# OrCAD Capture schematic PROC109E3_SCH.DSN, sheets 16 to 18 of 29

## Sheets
16 16. ETHERNET_MUX_SoC_ADC_IN: size C; title: ETHERNET DATA MUX & ADC INPUTS
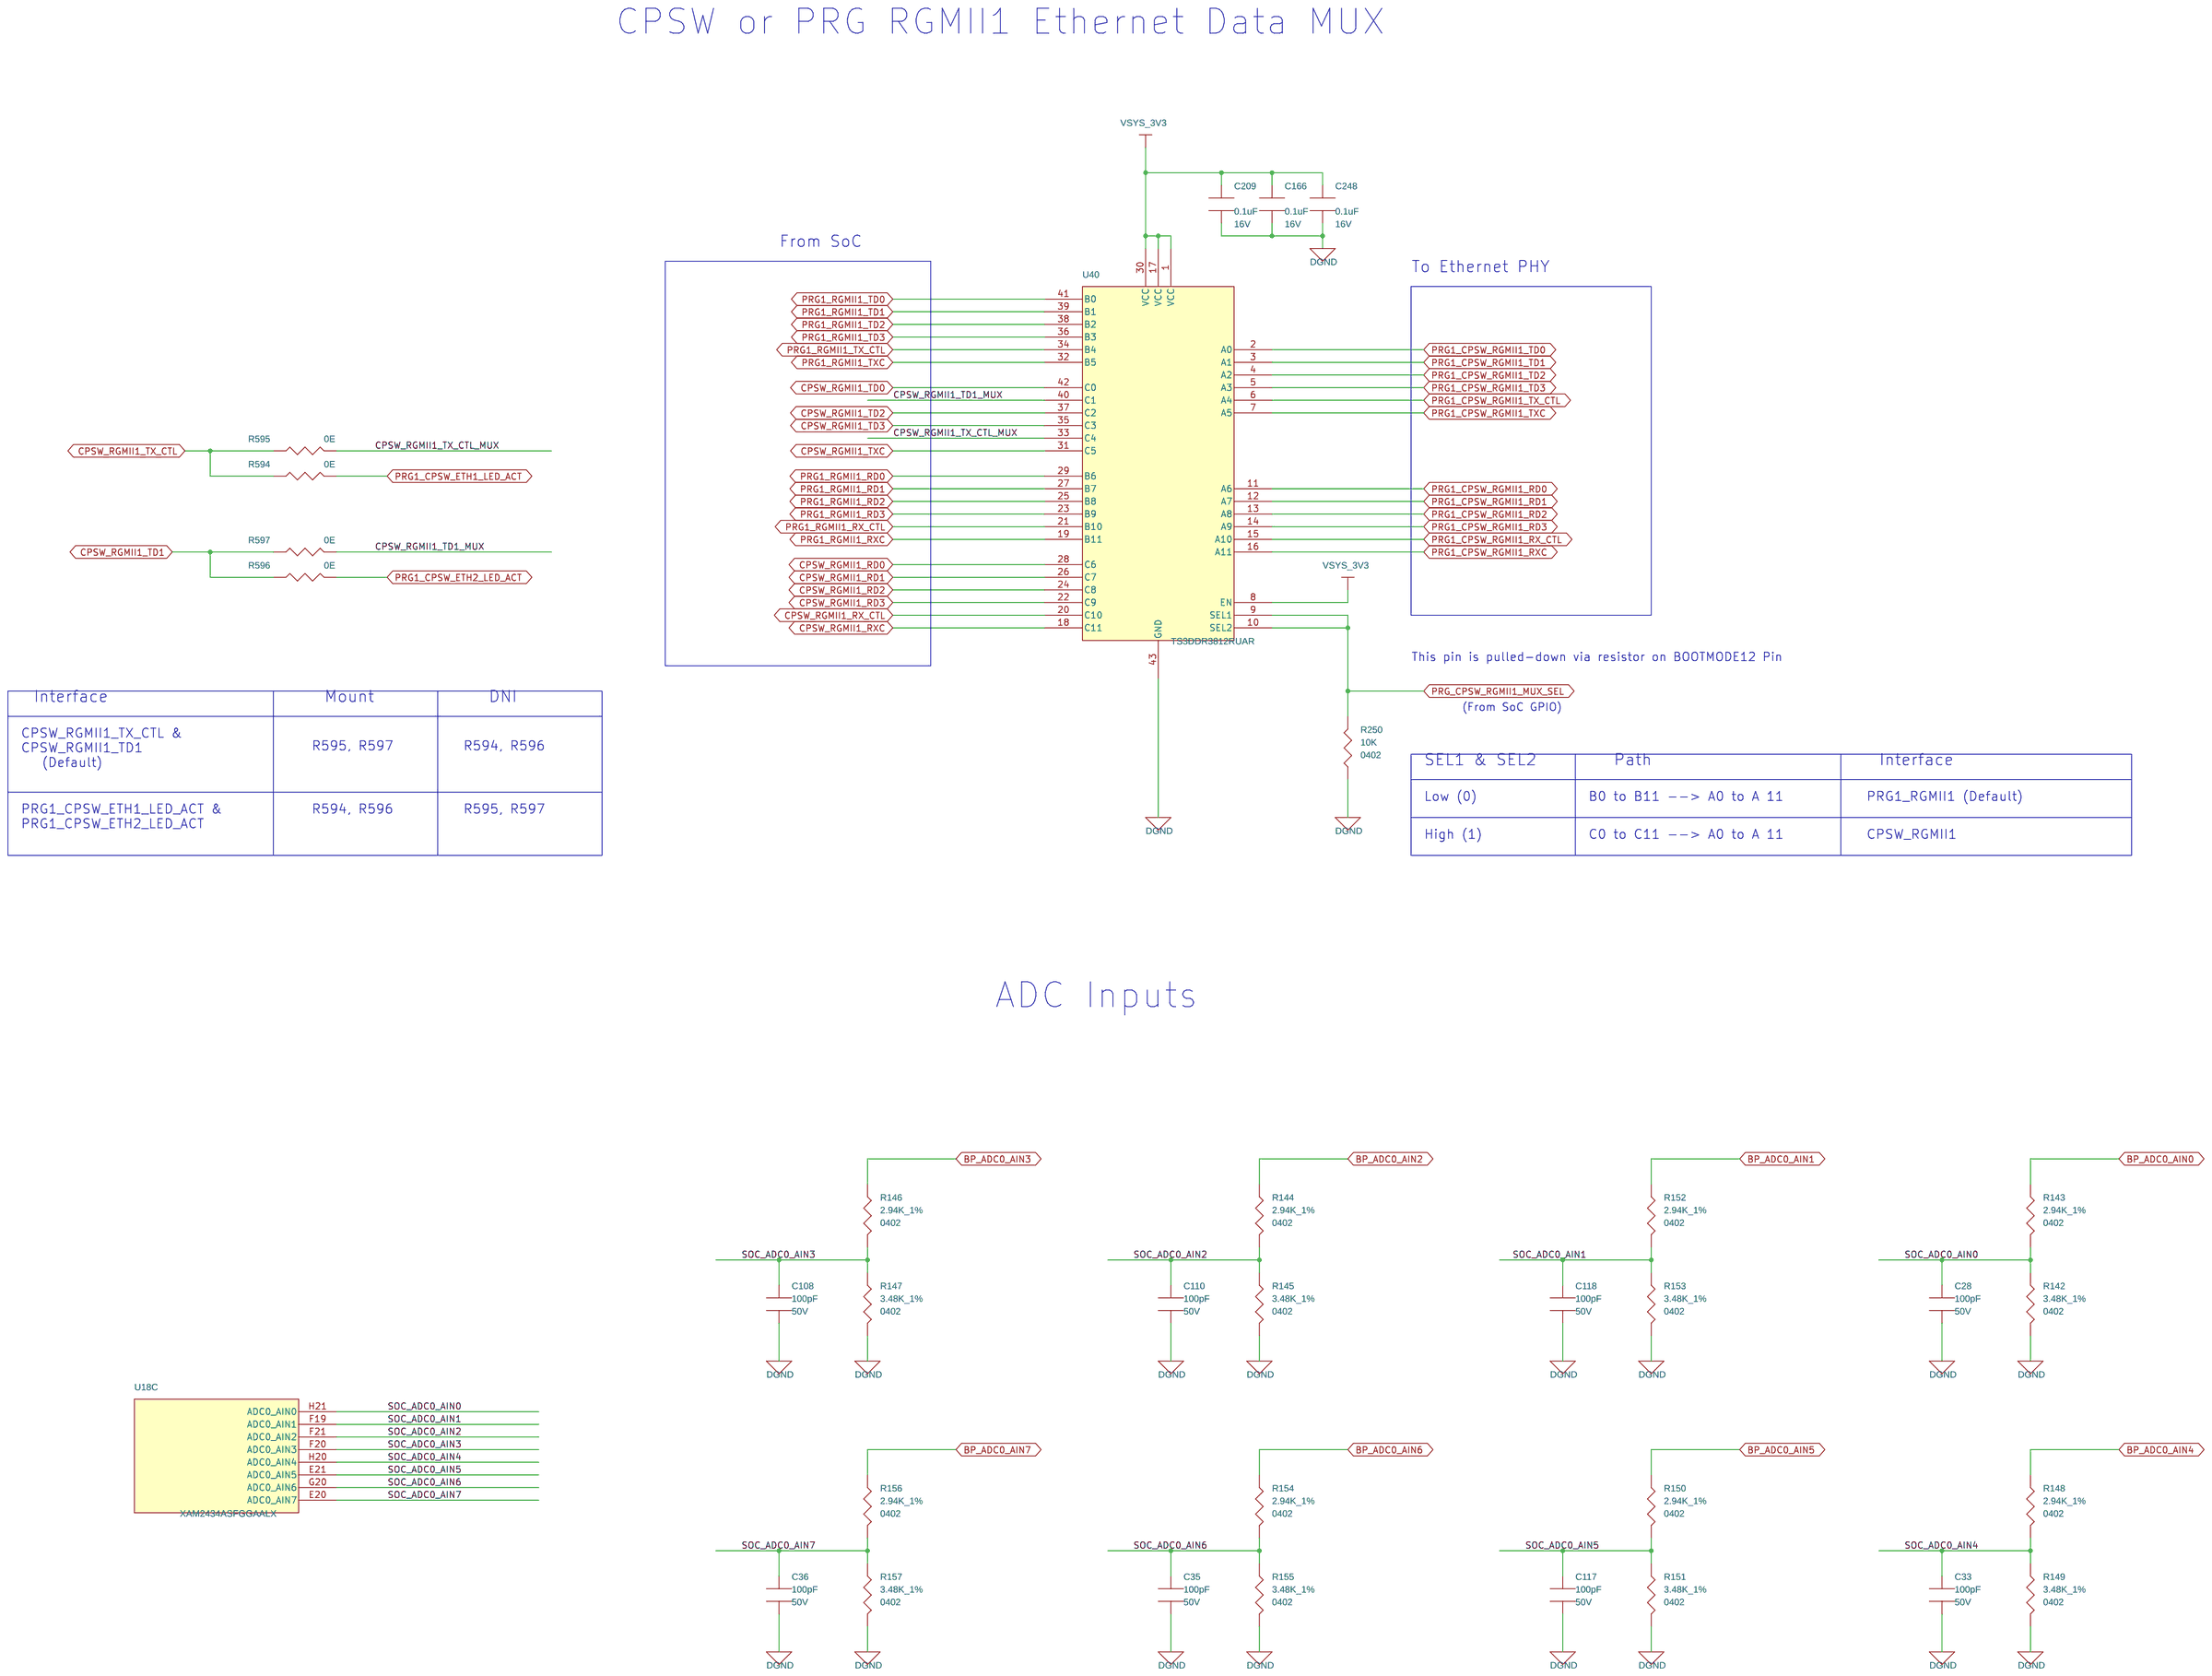
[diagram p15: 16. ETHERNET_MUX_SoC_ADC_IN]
17 17. CPSW_PRG_RGMII_1_EPHY: size C; title: PRG/CPSW RGMII1 ETHERNET PHY
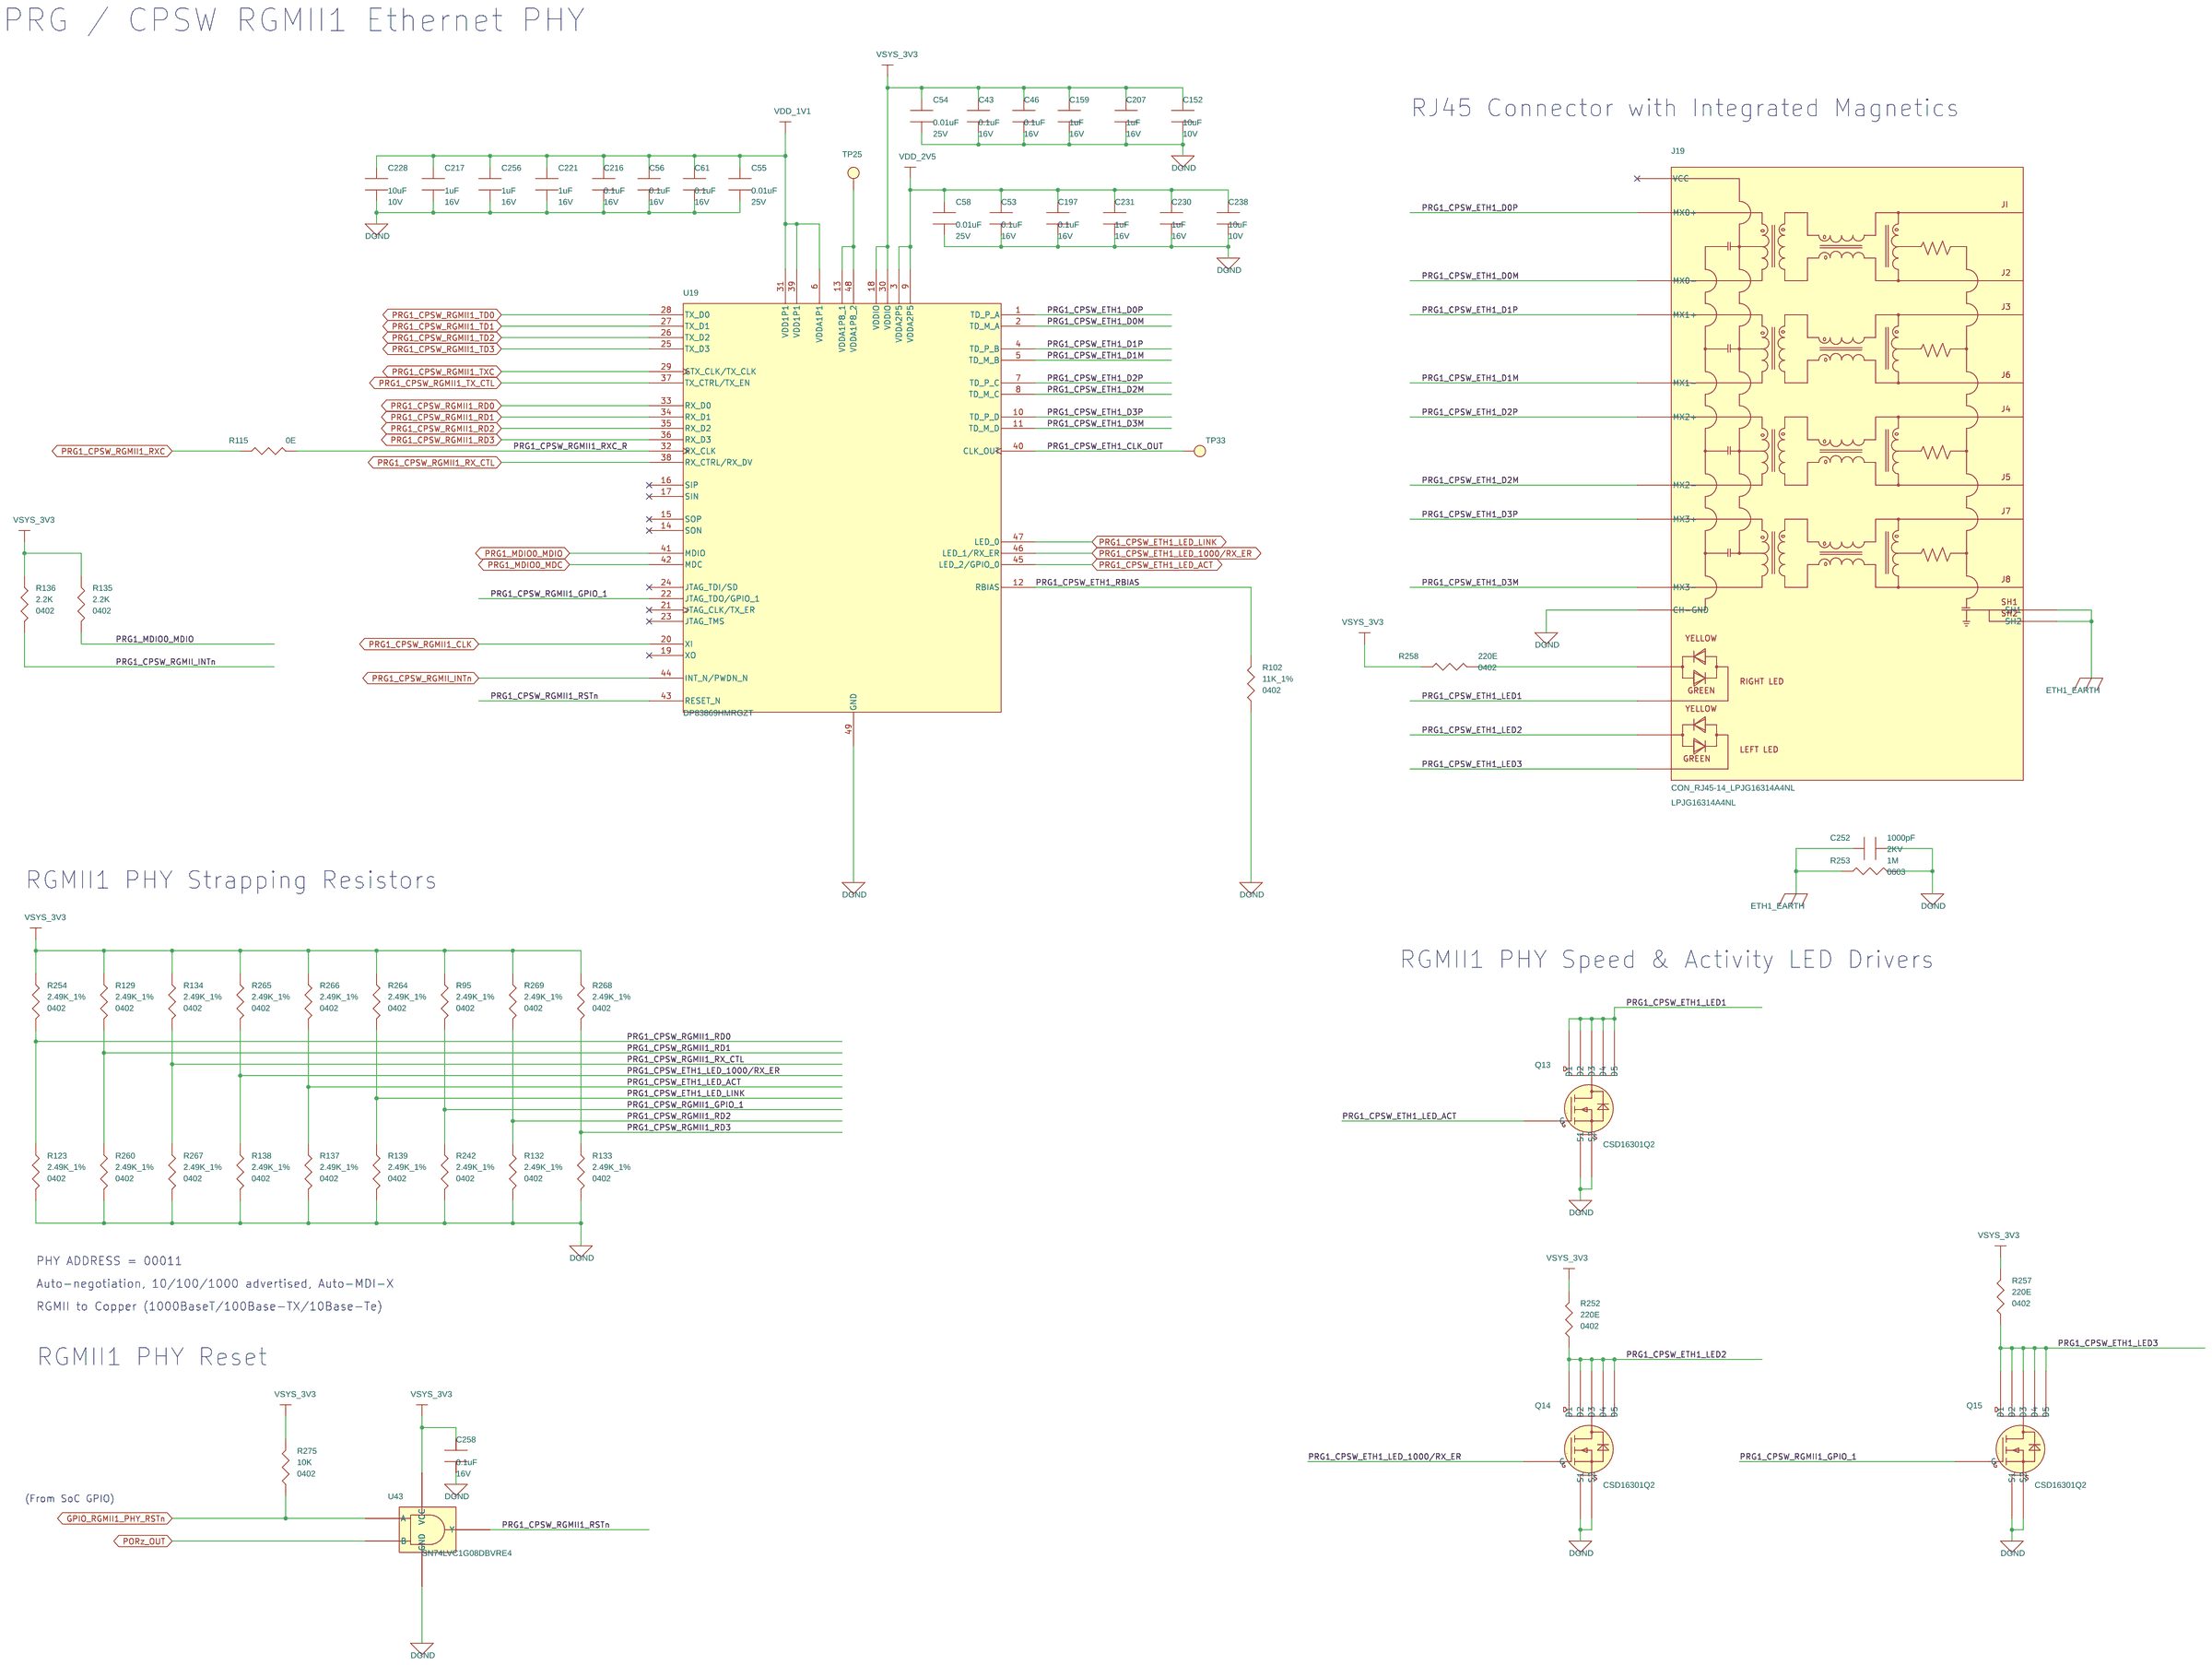
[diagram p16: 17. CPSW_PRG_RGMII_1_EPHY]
18 18. CPSW_PRG_RGMII_2_EPHY: size C; title: PRG/CPSW RGMII2 ETHERNET PHY
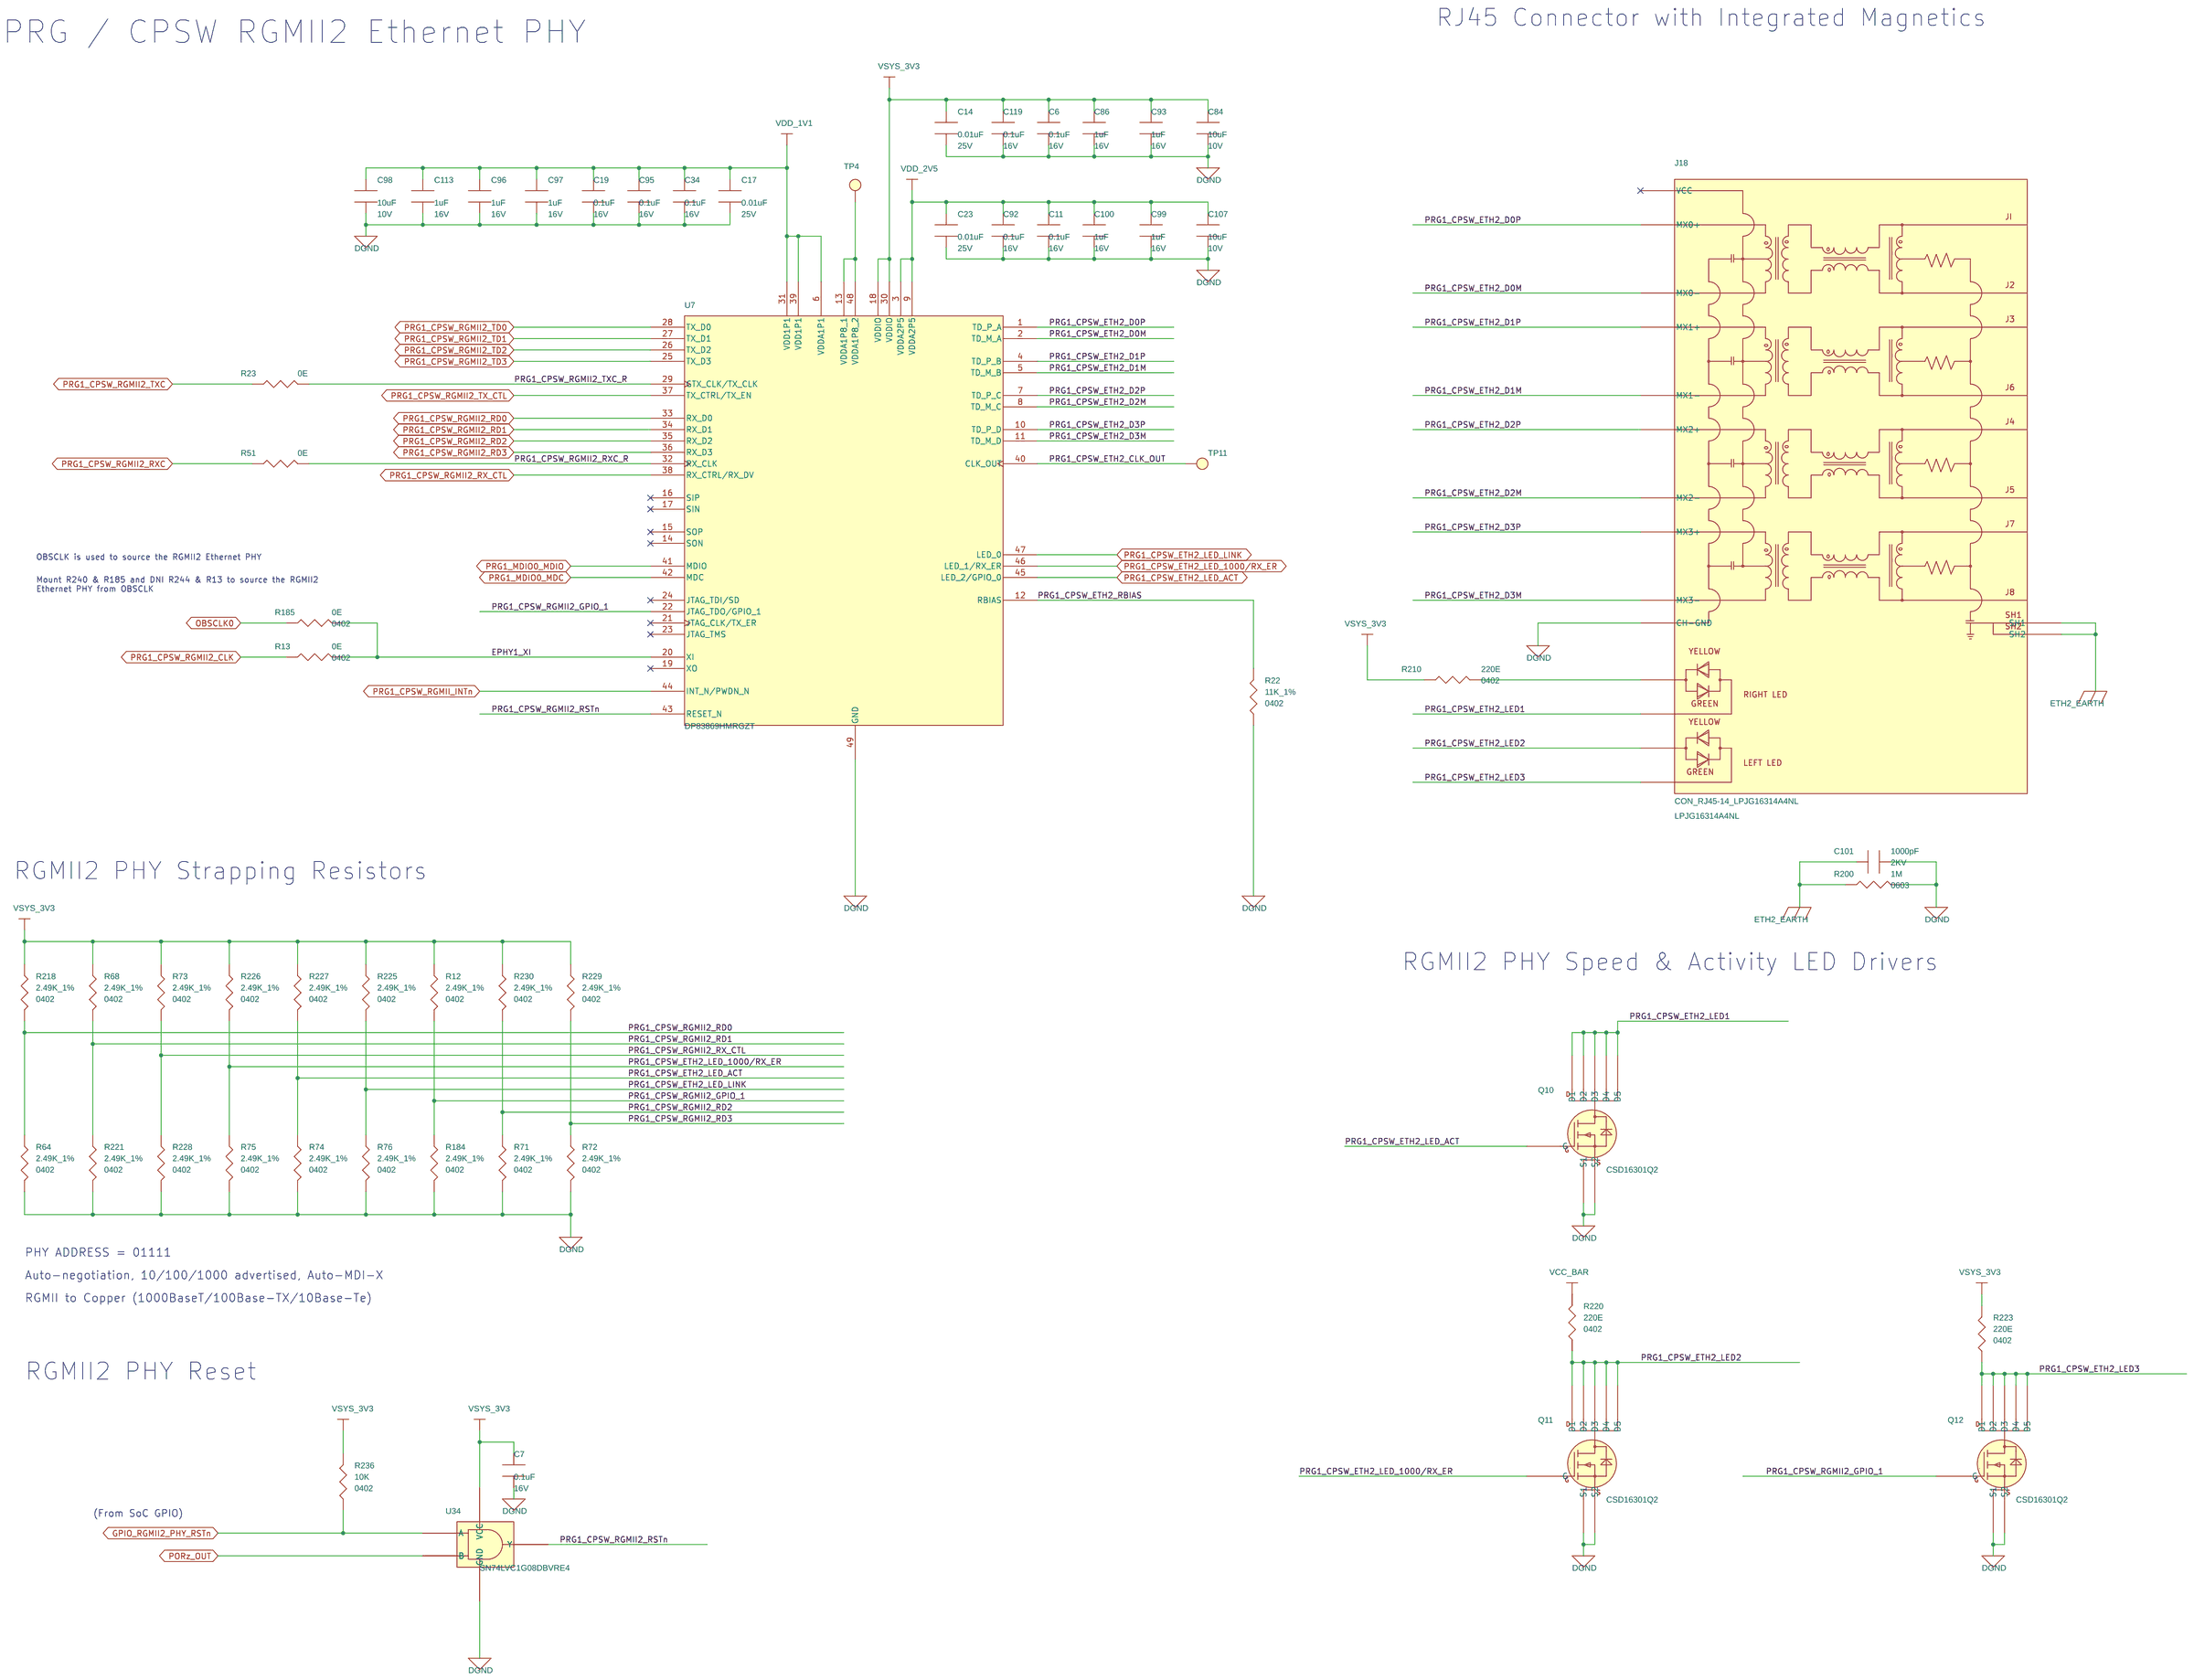
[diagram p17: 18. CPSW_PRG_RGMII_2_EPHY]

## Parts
sheet 16. ETHERNET_MUX_SoC_ADC_IN
C28  100pF  [CAP0402_0-75]
C33  100pF  [CAP0402_0-75]
C35  100pF  [CAP0402_0-75]
C36  100pF  [CAP0402_0-75]
C108  100pF  [CAP0402_0-75]
C110  100pF  [CAP0402_0-75]
C117  100pF  [CAP0402_0-75]
C118  100pF  [CAP0402_0-75]
C166  0.1uF  [CAP0201_0-5]
C209  0.1uF  [CAP0201_0-5]
C248  0.1uF  [CAP0201_0-5]
R142  3.48K_1%  [RES0402_0-5]
R143  2.94K_1%  [RES0402_0-5]
R144  2.94K_1%  [RES0402_0-5]
R145  3.48K_1%  [RES0402_0-5]
R146  2.94K_1%  [RES0402_0-5]
R147  3.48K_1%  [RES0402_0-5]
R148  2.94K_1%  [RES0402_0-5]
R149  3.48K_1%  [RES0402_0-5]
R150  2.94K_1%  [RES0402_0-5]
R151  3.48K_1%  [RES0402_0-5]
R152  2.94K_1%  [RES0402_0-5]
R153  3.48K_1%  [RES0402_0-5]
R154  2.94K_1%  [RES0402_0-5]
R155  3.48K_1%  [RES0402_0-5]
R156  2.94K_1%  [RES0402_0-5]
R157  3.48K_1%  [RES0402_0-5]
R250  10K  [RES0402_0-5]
R594  0E  [RES0402_0-5]
R595  0E  [RES0402_0-5]
R596  0E  [RES0402_0-5]
R597  0E  [RES0402_0-5]
U40  TS3DDR3812RUAR  [TQFN42_19-68_140X360_0-8]
sheet 17. CPSW_PRG_RGMII_1_EPHY
C43  0.1uF  [CAP0201_0-5]
C46  0.1uF  [CAP0201_0-5]
C53  0.1uF  [CAP0201_0-5]
C54  0.01uF  [CAP0201_0-5]
C55  0.01uF  [CAP0201_0-5]
C56  0.1uF  [CAP0201_0-5]
C58  0.01uF  [CAP0201_0-5]
C61  0.1uF  [CAP0201_0-5]
C152  10uF  [CAP0402_0-75]
C159  1uF  [CAP0201_0-5]
C197  0.1uF  [CAP0201_0-5]
C207  1uF  [CAP0201_0-5]
C216  0.1uF  [CAP0201_0-5]
C217  1uF  [CAP0201_0-5]
C221  1uF  [CAP0201_0-5]
C228  10uF  [CAP0402_0-75]
C230  1uF  [CAP0201_0-5]
C231  1uF  [CAP0201_0-5]
C238  10uF  [CAP0402_0-75]
C252  1000pF  [CAP1210_1-5]
C256  1uF  [CAP0201_0-5]
C258  0.1uF  [CAP0201_0-5]
J19  CON_RJ45-14_LPJG16314A4NL  [CON_RJ45-14_LPJG16314A4NL_S_R_T_13-6]
Q13  CSD16301Q2  [WSON6_CSD13202Q2_80X80_0-8]
Q14  CSD16301Q2  [WSON6_CSD13202Q2_80X80_0-8]
Q15  CSD16301Q2  [WSON6_CSD13202Q2_80X80_0-8]
R95  2.49K_1%  [RES0402_0-5]
R102  11K_1%  [RES0402_0-5]
R115  0E  [RES0402_0-5]
R123  2.49K_1%  [RES0402_0-5]
R129  2.49K_1%  [RES0402_0-5]
R132  2.49K_1%  [RES0402_0-5]
R133  2.49K_1%  [RES0402_0-5]
R134  2.49K_1%  [RES0402_0-5]
R135  2.2K  [RES0402_0-5]
R136  2.2K  [RES0402_0-5]
R137  2.49K_1%  [RES0402_0-5]
R138  2.49K_1%  [RES0402_0-5]
R139  2.49K_1%  [RES0402_0-5]
R242  2.49K_1%  [RES0402_0-5]
R252  220E  [RES0402_0-5]
R253  1M  [RES0603_0-75]
R254  2.49K_1%  [RES0402_0-5]
R257  220E  [RES0402_0-5]
R258  220E  [RES0402_0-5]
R260  2.49K_1%  [RES0402_0-5]
R264  2.49K_1%  [RES0402_0-5]
R265  2.49K_1%  [RES0402_0-5]
R266  2.49K_1%  [RES0402_0-5]
R267  2.49K_1%  [RES0402_0-5]
R268  2.49K_1%  [RES0402_0-5]
R269  2.49K_1%  [RES0402_0-5]
R275  10K  [RES0402_0-5]
TP25  TP20_SMD  [TP20_SMD]
TP33  TP20_SMD  [TP20_SMD]
U19  DP83869HMRGZT  [QFN48_19-68_280X280_1_EP4-2]
U43  SN74LVC1G08DBVRE4  [SOT23-5]
sheet 18. CPSW_PRG_RGMII_2_EPHY
C6  0.1uF  [CAP0201_0-5]
C7  0.1uF  [CAP0201_0-5]
C11  0.1uF  [CAP0201_0-5]
C14  0.01uF  [CAP0201_0-5]
C17  0.01uF  [CAP0201_0-5]
C19  0.1uF  [CAP0201_0-5]
C23  0.01uF  [CAP0201_0-5]
C34  0.1uF  [CAP0201_0-5]
C84  10uF  [CAP0402_0-75]
C86  1uF  [CAP0201_0-5]
C92  0.1uF  [CAP0201_0-5]
C93  1uF  [CAP0201_0-5]
C95  0.1uF  [CAP0201_0-5]
C96  1uF  [CAP0201_0-5]
C97  1uF  [CAP0201_0-5]
C98  10uF  [CAP0402_0-75]
C99  1uF  [CAP0201_0-5]
C100  1uF  [CAP0201_0-5]
C101  1000pF  [CAP1210_1-5]
C107  10uF  [CAP0402_0-75]
C113  1uF  [CAP0201_0-5]
C119  0.1uF  [CAP0201_0-5]
J18  CON_RJ45-14_LPJG16314A4NL  [CON_RJ45-14_LPJG16314A4NL_S_R_T_13-6]
Q10  CSD16301Q2  [WSON6_CSD13202Q2_80X80_0-8]
Q11  CSD16301Q2  [WSON6_CSD13202Q2_80X80_0-8]
Q12  CSD16301Q2  [WSON6_CSD13202Q2_80X80_0-8]
R12  2.49K_1%  [RES0402_0-5]
R13  0E  [RES0402_0-5]
R22  11K_1%  [RES0402_0-5]
R23  0E  [RES0402_0-5]
R51  0E  [RES0402_0-5]
R64  2.49K_1%  [RES0402_0-5]
R68  2.49K_1%  [RES0402_0-5]
R71  2.49K_1%  [RES0402_0-5]
R72  2.49K_1%  [RES0402_0-5]
R73  2.49K_1%  [RES0402_0-5]
R74  2.49K_1%  [RES0402_0-5]
R75  2.49K_1%  [RES0402_0-5]
R76  2.49K_1%  [RES0402_0-5]
R184  2.49K_1%  [RES0402_0-5]
R185  0E  [RES0402_0-5]
R200  1M  [RES0603_0-75]
R210  220E  [RES0402_0-5]
R218  2.49K_1%  [RES0402_0-5]
R220  220E  [RES0402_0-5]
R221  2.49K_1%  [RES0402_0-5]
R223  220E  [RES0402_0-5]
R225  2.49K_1%  [RES0402_0-5]
R226  2.49K_1%  [RES0402_0-5]
R227  2.49K_1%  [RES0402_0-5]
R228  2.49K_1%  [RES0402_0-5]
R229  2.49K_1%  [RES0402_0-5]
R230  2.49K_1%  [RES0402_0-5]
R236  10K  [RES0402_0-5]
TP4  TP20_SMD  [TP20_SMD]
TP11  TP20_SMD  [TP20_SMD]
U7  DP83869HMRGZT  [QFN48_19-68_280X280_1_EP4-2]
U34  SN74LVC1G08DBVRE4  [SOT23-5]
sheet 25. SOC_ANALOG_POWER_DECAPs
U18  XAM2434ASFGGAALX  [BGA293_19-68_440X440_1]  (sections A,B,C,D,E,F,G,H,I,J,K,L,M)

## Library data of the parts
C28 C33 C35 C36 C108 C110 C117 C118 = CAP: CAP CERAMIC 100pF 50V 1% C0G(NP0) AUTO 0402; Chkd/date: MANIRAJA/240521; Crtd /date: ALVY/210521; Custom_Duty: 15%; Customs_HS_Code: 85322990; Distributor_name: MOUSER; Distributor_part_number: 81-GRT1555C1H101FA2D; Footprint Path: Y:\MIS_DATABASE\Library\ALTIUM_TOOL\PCB_FOOTPRINTS\Altium_Footprint_Lib.PcbLib; Height: 0.55MM; Library Path: Y:\MIS_DATABASE\Library\ALTIUM_TOOL\SCHEMATICS_PARTS\MS_DISCRETE_Library.schlib; Mfr_name: MURATA; Mfr_part_number: GRT1555C1H101FA02D; Mistral Part No: 120019080008-R; Package: 0402; Part_type: CAPACITORS\CERAMIC; Project: AM243x_LP_BRD; RoHS: RoHS; Temperature: -55°C+125°C; Tolerance: 1%; Voltage: 50V; Wattage: NA; Weight: 1.6mg; Datasheet: Y:\MIS_DATABASE\DATASHEETS\CAPACITORS\GRT1555C1H101FA02.PDF
C166 C209 C248 = CAP: CAP CERAMIC 0.1uF 16V 10% X5R 0201; Chkd/date: MANIRAJA/230118; Crtd /date: MANIRAJA/230118; Custom_Duty: 15%; Customs_HS_Code: 85322990; Distributor_name: DIGIKEY; Distributor_part_number: 490-14305-1-ND; Footprint Path: Y:\MIS_DATABASE\Library\ALTIUM_TOOL\PCB_FOOTPRINTS\Altium_Footprint_Lib.PcbLib; Height: 0.33MM; Library Path: Y:\MIS_DATABASE\Library\ALTIUM_TOOL\SCHEMATICS_PARTS\MS_DISCRETE_Library.schlib; Mfr_name: MURATA; Mfr_part_number: GRM033R61C104KE14D; Mistral Part No: 120009030072-R; Package: 0201; Part_type: CAPACITORS\CERAMIC; Project: TI_MAXIE_CPB; RoHS: RoHS; Temperature: -55°C+85°C; Tolerance: 10%; Voltage: 16V; Wattage: NA; Weight: 0.33mg; Datasheet: Y:\MIS_DATABASE\DATASHEETS\CAPACITORS\GRM033R61C104KE14.PDF
R142 R145 R147 R149 R151 R153 R155 R157 = RESISTOR: RES 3.48K 1/16W 1% 0402; Chkd/date: ALVY/091220; Crtd /date: MANIRAJA/091220; Custom_Duty: 15%; Customs_HS_Code: 85332119; Distributor_name: DIGIKEY; Distributor_part_number: YAG3148CT-ND; Footprint Path: Y:\MIS_DATABASE\Library\ALTIUM_TOOL\PCB_FOOTPRINTS\Altium_Footprint_Lib.PcbLib; Height: 0.40MM; Library Path: Y:\MIS_DATABASE\Library\ALTIUM_TOOL\SCHEMATICS_PARTS\MS_DISCRETE_Library.schlib; Mfr_name: YAGEO AMERICA; Mfr_part_number: RC0402FR-073K48L; Mistral Part No: 110019120035-R; Package: 0402; Part_type: RESISTORS\FIXED; Project: TI_AM243x LP EVM; RoHS: RoHS; Temperature: -55°C+155°C; Tolerance: 1%; Voltage: NA; Wattage: 1/16W; Weight: 0.65mg; Datasheet: Y:\MIS_DATABASE\DATASHEETS\RESISTORS\RCXXXXL-SER_MAR18.PDF
R143 R144 R146 R148 R150 R152 R154 R156 = RESISTOR: RES 2.94K 1/10W 1% 0402; Chkd/date: MANIRAJA/080319; Crtd /date: MANIRAJA/080319; Custom_Duty: 15%; Customs_HS_Code: 85332119; Distributor_name: DIGIKEY; Distributor_part_number: P2.94KLCT-ND; Footprint Path: Y:\MIS_DATABASE\Library\ALTIUM_TOOL\PCB_FOOTPRINTS\Altium_Footprint_Lib.PcbLib; Height: 0.40MM; Library Path: Y:\MIS_DATABASE\Library\ALTIUM_TOOL\SCHEMATICS_PARTS\MS_DISCRETE_Library.schlib; Mfr_name: PANASONIC-ECG; Mfr_part_number: ERJ-2RKF2941X; Mistral Part No: 110009030460-R; Package: 0402; Part_type: RESISTORS\FIXED; Project: TELEMETRY ENCODER; RoHS: RoHS; Temperature: -55°C+155°C; Tolerance: 1%; Voltage: NA; Wattage: 1/10W; Weight: 0.8mg; Datasheet: Y:\MIS_DATABASE\DATASHEETS\RESISTORS\PAN-ERJSER_NOV17.PDF
R236 R250 R275 = RESISTOR: RES 10K 1/16W 5% 0402; Chkd/date: VASANTHA/061216; Crtd /date: MAZHAR/230805; Custom_Duty: 15%; Customs_HS_Code: 85332119; Distributor_name: DIGIKEY; Distributor_part_number: 311-10KJRCT-ND; Footprint Path: Y:\MIS_DATABASE\Library\ALTIUM_TOOL\PCB_FOOTPRINTS\Altium_Footprint_Lib.PcbLib; Height: 0.40MM; Library Path: Y:\MIS_DATABASE\Library\ALTIUM_TOOL\SCHEMATICS_PARTS\MS_DISCRETE_Library.schlib; Mfr_name: YAGEO AMERICA; Mfr_part_number: RC0402JR-0710KL; Mistral Part No: 110011060021-R; Package: 0402; Part_type: RESISTORS\FIXED; Project: HSE; RoHS: RoHS; Temperature: -55°C+155°C; Tolerance: 5%; Voltage: NA; Wattage: 1/16W; Weight: 0.65mg; Datasheet: Y:\MIS_DATABASE\DATASHEETS\RESISTORS\RCXXXXL-SER_MAR18.PDF
R13 R185 R594-R597 = RESISTOR: RES 0E 1/16W 5% 0402; Chkd/date: VASANTHA/291216; Crtd /date: CHAITHANYA/300911; Custom_Duty: 15%; Customs_HS_Code: 85332119; Distributor_name: DIGIKEY; Distributor_part_number: 311-0.0JRCT-ND; Footprint Path: Y:\MIS_DATABASE\Library\ALTIUM_TOOL\PCB_FOOTPRINTS\Altium_Footprint_Lib.PcbLib; Height: 0.40MM; Library Path: Y:\MIS_DATABASE\Library\ALTIUM_TOOL\SCHEMATICS_PARTS\MS_DISCRETE_Library.schlib; Mfr_name: YAGEO AMERICA; Mfr_part_number: RC0402JR-070RL; Mistral Part No: 110011090036-R; Package: 0402; Part_type: RESISTORS\FIXED; Project: VP-4000-PROCESSOR; RoHS: RoHS; Temperature: -55°C+155°C; Tolerance: 5%; Voltage: NA; Wattage: 1/16W; Weight: 0.65mg; Datasheet: Y:\MIS_DATABASE\DATASHEETS\RESISTORS\RCXXXXL-SER_MAR18.PDF
U40 = TS3DDR3812RUAR_WQFN42: IC 12-CH 1:2 MUX/DEMUX SWITCH FOR DDR3 APPLICATION WQFN42; Chkd/date: MANIRAJA/250918; Crtd /date: ALVY/250918; Custom_Duty: 15%; Customs_HS_Code: 85423100; Distributor_name: DIGIKEY; Distributor_part_number: 296-28307-1-ND; Footprint Path: Y:\MIS_DATABASE\Library\ALTIUM_TOOL\PCB_FOOTPRINTS\Altium_Footprint_Lib.PcbLib; Height: 0.80MM; Library Path: Y:\MIS_DATABASE\Library\ALTIUM_TOOL\SCHEMATICS_PARTS\MS_COMBINATIONAL_Library.schlib; Mfr_name: TEXAS INSTRUMENTS; Mistral Part No: 141018090023-R; Package: WQFN42; Part_type: ICS\DIGITAL\COMBINATIONAL; Project: TI_J7ES_EVM_CP; RoHS: RoHS; Temperature: -40°C+85°C; Tolerance: NA; Voltage: NA; Wattage: NA; Weight: 54.8mg; Datasheet: Y:\MIS_DATABASE\DATASHEETS\ICS\DIGITAL\COMBINATIONAL\TS3DDR3812.PDF
C6 C7 C11 C19 C34 C43 C46 C53 C56 C61 C92 C95 C119 C197 C216 C258 = CAP: CAP CERAMIC 0.1uF 16V 10% X5R 0201; Alt_Mfr_name: YAGEO AMERICA; Alt_Mfr_part_number: CC0402KRX5R8BB104; Chkd/date: MANIRAJA/230118; Crtd /date: MANIRAJA/230118; Custom_Duty: 15%; Customs_HS_Code: 85322990; Distributor_name: DIGIKEY; Distributor_part_number: 490-14305-1-ND; Footprint Path: Y:\MIS_DATABASE\Library\ALTIUM_TOOL\PCB_FOOTPRINTS\Altium_Footprint_Lib.PcbLib; Height: 0.33MM; Library Path: Y:\MIS_DATABASE\Library\ALTIUM_TOOL\SCHEMATICS_PARTS\MS_DISCRETE_Library.schlib; Mfr_name: MURATA; Mfr_part_number: GRM033R61C104KE14D; Mistral Part No: 120009030072-R; Package: 0201; Part_type: CAPACITORS\CERAMIC; Project: TI_MAXIE_CPB; RoHS: RoHS; Temperature: -55°C+85°C; Tolerance: 10%; Voltage: 16V; Wattage: NA; Weight: 0.33mg; Datasheet: Y:\MIS_DATABASE\DATASHEETS\CAPACITORS\GRM033R61C104KE14.PDF
C14 C17 C23 C54 C55 C58 = CAP: CAP CERAMIC 0.01uF 25V 10% X7R 0201; Chkd/date: MANIRAJA/080519; Crtd /date: ALVY/080519; Custom_Duty: 15%; Customs_HS_Code: 85322990; Distributor_name: DIGIKEY; Distributor_part_number: 490-14454-1-ND; Footprint Path: Y:\MIS_DATABASE\Library\ALTIUM_TOOL\PCB_FOOTPRINTS\Altium_Footprint_Lib.PcbLib; Height: 0.33MM; Library Path: Y:\MIS_DATABASE\Library\ALTIUM_TOOL\SCHEMATICS_PARTS\MS_DISCRETE_Library.schlib; Mfr_name: MURATA; Mfr_part_number: GRM033R71E103KE14D; Mistral Part No: 120019050002-R; Package: 0201; Part_type: CAPACITORS\CERAMIC; Project: BRUKER_SD820_COMMONDO; RoHS: RoHS; Temperature: -55°C+125°C; Tolerance: 10%; Voltage: 25V; Wattage: NA; Weight: 0.33mg; Datasheet: Y:\MIS_DATABASE\DATASHEETS\CAPACITORS\GRM033R71E103KE14.PDF
C84 C98 C107 C152 C228 C238 = CAP: CAP CERAMIC 10uF 10V 20% X5R 0402; Chkd/date: MANIRAJA/300520; Crtd /date: ALVY/260520; Custom_Duty: 15%; Customs_HS_Code: 85322990; Distributor_name: DIGIKEY; Distributor_part_number: 490-GRM155R61A106ME11DTR-ND; Footprint Path: Y:\MIS_DATABASE\Library\ALTIUM_TOOL\PCB_FOOTPRINTS\Altium_Footprint_Lib.PcbLib; Height: 0.55MM; Library Path: Y:\MIS_DATABASE\Library\ALTIUM_TOOL\SCHEMATICS_PARTS\MS_DISCRETE_Library.schlib; Mfr_name: MURATA; Mfr_part_number: GRM155R61A106ME11D; Mistral Part No: 120013110019-R; Package: 0402; Part_type: CAPACITORS\CERAMIC; Project: QCS610_NANOSOM; RoHS: RoHS; Temperature: -55°C+85°C; Tolerance: 20%; Voltage: 10V; Wattage: NA; Weight: 3.1mg; Datasheet: Y:\MIS_DATABASE\DATASHEETS\CAPACITORS\MURATA-GXX-SER_NOV17.PDF
C86 C93 C96 C97 C99 C100 C113 C159 C207 C217 C221 C230 C231 C256 = CAP: CAP CERAMIC 1uF 16V 20% X5R 0201; Chkd/date: MANIRAJA/300520; Crtd /date: ALVY/260520; Custom_Duty: 15%; Customs_HS_Code: 85322990; Distributor_name: DIGIKEY; Distributor_part_number: 490-18654-1-ND; Footprint Path: Y:\MIS_DATABASE\Library\ALTIUM_TOOL\PCB_FOOTPRINTS\Altium_Footprint_Lib.PcbLib; Height: 0.39MM; Library Path: Y:\MIS_DATABASE\Library\ALTIUM_TOOL\SCHEMATICS_PARTS\MS_DISCRETE_Library.schlib; Mfr_name: MURATA; Mfr_part_number: GRM033R61C105ME15D; Mistral Part No: 120018090038-R; Package: 0201; Part_type: CAPACITORS\CERAMIC; Project: QCS610_NANOSOM; RoHS: RoHS; Temperature: -55°C+85°C; Tolerance: 20%; Voltage: 16V; Wattage: NA; Weight: 0.33mg; Datasheet: Y:\MIS_DATABASE\DATASHEETS\CAPACITORS\GRM033R61C105ME15.PDF
C101 C252 = CAP: CAP CERAMIC 1000pF 2KV 10% X7R 1210; Chkd/date: ALVY/071220; Crtd /date: MANIRAJA/071220; Custom_Duty: 15%; Customs_HS_Code: 85322990; Distributor_name: DIGIKEY; Distributor_part_number: 732-12130-1-ND; Footprint Path: Y:\MIS_DATABASE\Library\ALTIUM_TOOL\PCB_FOOTPRINTS\Altium_Footprint_Lib.PcbLib; Height: 1.35MM; Library Path: Y:\MIS_DATABASE\Library\ALTIUM_TOOL\SCHEMATICS_PARTS\MS_DISCRETE_Library.schlib; Mfr_name: WURTH ELEKTRONIK; Mfr_part_number: 885342209009; Mistral Part No: 120020120008-R; Package: 1210; Part_type: CAPACITORS\CERAMIC; Project: TI_AM243x LP EVM; RoHS: RoHS; Temperature: -55°C+125°C; Tolerance: 10%; Voltage: 2KV; Wattage: NA; Weight: 19.234mg; Datasheet: Y:\MIS_DATABASE\DATASHEETS\CAPACITORS\885342209009.PDF
J18 J19 = CON_RJ45-14_LPJG16314A4NL: CON RJ-45 FEMALE 14POS RT TH; Chkd/date: VASANTHA/150714; Crtd /date: BALACHANDAR/120614; Custom_Duty: 24%; Customs_HS_Code: 85369090; Distributor_name: NA; Distributor_part_number: NA; Footprint Path: Y:\MIS_DATABASE\Library\ALTIUM_TOOL\PCB_FOOTPRINTS\Altium_Footprint_Lib.PcbLib; Height: 13.60MM; Library Path: Y:\MIS_DATABASE\Library\ALTIUM_TOOL\SCHEMATICS_PARTS\MS_CONNECTOR_Library.schlib; Mfr_name: LINK-PP; Mfr_part_number: LPJG16314A4NL; Mistral Part No: 150014060029-R; Package: THRU-HOLE; Part_type: CONNECTOR\JACK; Project: AEGIS; RoHS: RoHS; Temperature: -0°C+70°C; Tolerance: NA; Voltage: NA; Wattage: NA; Weight: NA; Datasheet: Y:\MIS_DATABASE\DATASHEETS\CONNECTORS\LPJG16314A4NL.PDF
Q10-Q15 = MOSFET_CSD17313Q2: IC MOSFET N-CHANNEL NEXFET 25V WSON6; Chkd/date: ALVY/071220; Crtd /date: MANIRAJA/071220; Custom_Duty: 15%; Customs_HS_Code: 85423100; Distributor_name: DIGIKEY; Distributor_part_number: 296-25260-1-ND; Footprint Path: Y:\MIS_DATABASE\Library\ALTIUM_TOOL\PCB_FOOTPRINTS\Altium_Footprint_Lib.PcbLib; Height: 0.80MM; Library Path: Y:\MIS_DATABASE\Library\ALTIUM_TOOL\SCHEMATICS_PARTS\MS_MOSFET_Library.schlib; Mfr_name: TEXAS INSTRUMENTS; Mistral Part No: 142020120008-R; Package: WSON6; Part_type: ICS\POWER\MOSFET; Project: TI_AM243x LP EVM; RoHS: RoHS; Temperature: -55°C+150°C; Tolerance: NA; Voltage: NA; Wattage: NA; Weight: 8.7mg; Datasheet: Y:\MIS_DATABASE\DATASHEETS\ICS\POWER\CSD16301Q2.PDF
R12 R64 R68 R71-R76 R95 R123 R129 R132-R134 R137-R139 R184 R218 R221 R225-R230 R242 R254 R260 R264-R269 = RESISTOR: RES 2.49K 1/16W 1% 0402; Chkd/date: VASANTHA/270516; Crtd /date: VASANTHA/270516; Custom_Duty: 15%; Customs_HS_Code: 85332119; Distributor_name: DIGIKEY; Distributor_part_number: 311-2.49KLRCT-ND; Footprint Path: Y:\MIS_DATABASE\Library\ALTIUM_TOOL\PCB_FOOTPRINTS\Altium_Footprint_Lib.PcbLib; Height: 0.40MM; Library Path: Y:\MIS_DATABASE\Library\ALTIUM_TOOL\SCHEMATICS_PARTS\MS_DISCRETE_Library.schlib; Mfr_name: YAGEO AMERICA; Mfr_part_number: RC0402FR-072K49L; Mistral Part No: 110016050020-R; Package: 0402; Part_type: RESISTORS\FIXED; Project: TMDXCSKCC; RoHS: RoHS; Temperature: -55°C+155°C; Tolerance: 1%; Voltage: NA; Wattage: 1/16W; Weight: 0.65mg; Datasheet: Y:\MIS_DATABASE\DATASHEETS\RESISTORS\RCXXXXL-SER_MAR18.PDF
R22 R102 = RESISTOR: RES 11K 1/16W 1% 0402; Chkd/date: VASANTHA/251115; Crtd /date: VASANTHA/251115; Custom_Duty: 15%; Customs_HS_Code: 85332119; Distributor_name: DIGIKEY; Distributor_part_number: 311-11.0KLRCT-ND; Footprint Path: Y:\MIS_DATABASE\Library\ALTIUM_TOOL\PCB_FOOTPRINTS\Altium_Footprint_Lib.PcbLib; Height: 0.40MM; Library Path: Y:\MIS_DATABASE\Library\ALTIUM_TOOL\SCHEMATICS_PARTS\MS_DISCRETE_Library.schlib; Mfr_name: YAGEO AMERICA; Mfr_part_number: RC0402FR-0711KL; Mistral Part No: 110015110012-R; Package: 0402; Part_type: RESISTORS\FIXED; Project: TI_VLAN_SWITCH; RoHS: RoHS; Temperature: -55°C+155°C; Tolerance: 1%; Voltage: NA; Wattage: 1/16W; Weight: 0.65mg; Datasheet: Y:\MIS_DATABASE\DATASHEETS\RESISTORS\RCXXXXL-SER_MAR18.PDF
R23 R51 R115 = RESISTOR: RES 0E 1/16W 5% 0402; Chkd/date: VASANTHA/291216; Crtd /date: CHAITHANYA/300911; Custom_Duty: 15%; Customs_HS_Code: 85332119; Distributor_name: DIGIKEY; Distributor_part_number: 311-0.0JRCT-ND; Footprint Path: Y:\MIS_DATABASE\Library\ALTIUM_TOOL\PCB_FOOTPRINTS\Altium_Footprint_Lib.PcbLib; Height: 0.40MM; Library Path: Y:\MIS_DATABASE\Library\ALTIUM_TOOL\SCHEMATICS_PARTS\MS_DISCRETE_Library.schlib; Mfr_name: YAGEO AMERICA; Mfr_part_number: RC0402JR-070RL; Mistral Part No: 110011090036-R; Package: 0402; Part_type: RESISTORS\FIXED; Project: VP-4000-PROCESSOR; RoHS: RoHS; SIGNAL_MODEL: RESISTOR_RES0402_0-5_0E_0E; Temperature: -55°C+155°C; Tolerance: 5%; Voltage: NA; Wattage: 1/16W; Weight: 0.65mg; Datasheet: Y:\MIS_DATABASE\DATASHEETS\RESISTORS\RCXXXXL-SER_MAR18.PDF
R135 R136 = RESISTOR: RES 2.2K 1/16W 5% 0402; Chkd/date: VASANTHA/061216; Crtd /date: BAVISH/021210; Custom_Duty: 15%; Customs_HS_Code: 85332119; Distributor_name: DIGIKEY; Distributor_part_number: 311-2.2KJRCT-ND; Footprint Path: Y:\MIS_DATABASE\Library\ALTIUM_TOOL\PCB_FOOTPRINTS\Altium_Footprint_Lib.PcbLib; Height: 0.40MM; Library Path: Y:\MIS_DATABASE\Library\ALTIUM_TOOL\SCHEMATICS_PARTS\MS_DISCRETE_Library.schlib; Mfr_name: YAGEO AMERICA; Mfr_part_number: RC0402JR-072K2L; Mistral Part No: 110010120018-R; Package: 0402; Part_type: RESISTORS\FIXED; Project: TE4; RoHS: RoHS; Temperature: -55°C+155°C; Tolerance: 5%; Voltage: NA; Wattage: 1/16W; Weight: 0.65mg; Datasheet: Y:\MIS_DATABASE\DATASHEETS\RESISTORS\RCXXXXL-SER_MAR18.PDF
R210 R220 R223 R252 R257 R258 = RESISTOR: RES 220E 1/16W 5% 0402; Chkd/date: ALVY/091220; Crtd /date: MANIRAJA/091220; Custom_Duty: 15%; Customs_HS_Code: 85332119; Distributor_name: DIGIKEY; Distributor_part_number: 311-220JRCT-ND; Footprint Path: Y:\MIS_DATABASE\Library\ALTIUM_TOOL\PCB_FOOTPRINTS\Altium_Footprint_Lib.PcbLib; Height: 0.40MM; Library Path: Y:\MIS_DATABASE\Library\ALTIUM_TOOL\SCHEMATICS_PARTS\MS_DISCRETE_Library.schlib; Mfr_name: YAGEO AMERICA; Mfr_part_number: RC0402JR-07220RL; Mistral Part No: 110020120013-R; Package: 0402; Part_type: RESISTORS\FIXED; Project: TI_AM243x LP EVM; RoHS: RoHS; Temperature: -55°C+155°C; Tolerance: 5%; Voltage: NA; Wattage: 1/16W; Weight: 0.65mg; Datasheet: Y:\MIS_DATABASE\DATASHEETS\RESISTORS\RCXXXXL-SER_MAR18.PDF
R200 R253 = RESISTOR: RES 1M 1/10W 5% 0603; Chkd/date: ALVY/091220; Crtd /date: MANIRAJA/091220; Custom_Duty: 15%; Customs_HS_Code: 85332119; Distributor_name: DIGIKEY; Distributor_part_number: 311-1.0MGRCT-ND; Footprint Path: Y:\MIS_DATABASE\Library\ALTIUM_TOOL\PCB_FOOTPRINTS\Altium_Footprint_Lib.PcbLib; Height: 0.55MM; Library Path: Y:\MIS_DATABASE\Library\ALTIUM_TOOL\SCHEMATICS_PARTS\MS_DISCRETE_Library.schlib; Mfr_name: YAGEO AMERICA; Mfr_part_number: RC0603JR-071ML; Mistral Part No: 110009030413-R; Package: 0603; Part_type: RESISTORS\FIXED; Project: TI_AM243x LP EVM; RoHS: RoHS; Temperature: -55°C+155°C; Tolerance: 5%; Voltage: NA; Wattage: 1/10W; Weight: 2mg; Datasheet: Y:\MIS_DATABASE\DATASHEETS\RESISTORS\RCXXXXL-SER_MAR18.PDF
TP4 TP11 TP25 TP33 = TESTPOINT: TESTPOINT CIR 20 SMD; Chkd/date: SHREESHAIL/171006; Crtd /date: MAZHAR/171006; Custom_Duty: NA; Customs_HS_Code: NA; Distributor_name: NA; Distributor_part_number: NA; Footprint Path: Y:\MIS_DATABASE\Library\ALTIUM_TOOL\PCB_FOOTPRINTS\Altium_Footprint_Lib.PcbLib; Height: NA; Library Path: Y:\MIS_DATABASE\Library\ALTIUM_TOOL\SCHEMATICS_PARTS\MS_DISCRETE_Library.schlib; MECHANICAL 3D STEP FILE: NA; Mfr_name: LOCAL; Mistral Part No: NA; Package: SMD; Project: BT MODULE_CSRBC04; RoHS: NA; Temperature: NA; Tolerance: NA; Voltage: NA; Wattage: NA; Weight: NA; Datasheet: NA
U7 U19 = DP83869HM_VQFN48: IC ETHERNET TRANSCEIVER 10/100/1000 WITH COPPER AND FIBRE INTERFACE VQFN48; Chkd/date: MANIRAJA/060519; Crtd /date: ALVY/060519; Custom_Duty: 15%; Customs_HS_Code: 85423100; Distributor_name: DIGIKEY; Distributor_part_number: 296-53377-1-ND; Footprint Path: Y:\MIS_DATABASE\Library\ALTIUM_TOOL\PCB_FOOTPRINTS\Altium_Footprint_Lib.PcbLib; Height: 1.00MM; Library Path: Y:\MIS_DATABASE\Library\ALTIUM_TOOL\SCHEMATICS_PARTS\MS_TELECOM_Library.schlib; Mfr_name: TEXAS INSTRUMENTS; Mistral Part No: 143019050002-R; Package: VQFN48; Part_type: ICS\TELECOM\TRANSCEIVER; Project: J7ES_ENET_DP83869HM_EXP; RoHS: RoHS; Temperature: -40°C+125°C; Tolerance: NA; Voltage: NA; Wattage: NA; Weight: NA; Datasheet: Y:\MIS_DATABASE\DATASHEETS\ICS\TELECOM\DP83869HM.PDF
U34 U43 = SN74LVC1G08DBVRE4_SOT23-5: IC SINGLE 2-INPUT POSITIVE AND GATE SOT23-5; Chkd/date: SUHAS/221010; Crtd /date: USMAN/151008; Custom_Duty: 15%; Customs_HS_Code: 85423100; Distributor_name: DIGIKEY; Distributor_part_number: SN74LVC1G08DBVRE4-ND; Height: 1.45MM; Mfr_name: TEXAS INSTRUMENTS; Mistral Part No: 141009060026-R; Part_type: ICS\DIGITAL\GATES; Project: KHAN_MAIN; RoHS: Sb/ Br FREE; Temperature: -40°C+85°C; Datasheet: Y:\MIS_DATABASE\DATASHEETS\ICS\DIGITAL\GATES\SN74LVC1G08.PDF
U18 = AM243X_SOC_LP_EVM_BGA293: IC AM243x SoC_LP_EVM MICROPROCESSOR BGA293; Chkd/date: MANIRAJA/131120; Crtd /date: ALVY/121120; Custom_Duty: 15%; Customs_HS_Code: 85423100; Distributor_name: NA; Distributor_part_number: NA; Footprint Path: Y:\MIS_DATABASE\Library\ALTIUM_TOOL\PCB_FOOTPRINTS\Altium_Footprint_Lib.PcbLib; Height: 1.00MM; Library Path: Y:\MIS_DATABASE\Library\ALTIUM_TOOL\SCHEMATICS_PARTS\MS_MICROPROCESSOR_Library.schlib; Library Ref: AM243x SoC_LP_EVM_BGA293; Mfr_name: TEXAS INSTRUMENTS; Mistral Part No: 141220110003; Package: BGA293; Part_type: ICS\DIGITAL\MICROPROCESSOR; Project: TI_AM243x LP EVM; RoHS: NA; Temperature: NA; Tolerance: NA; Voltage: NA; Wattage: NA; Weight: NA; Datasheet: Y:\MIS_DATABASE\DATASHEETS\ICS\DIGITAL\MICROCONTROLLER\AM243x SoC-FP.PDF

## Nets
DGND: C6.2 C7.2 C11.2 C14.2 C17.2 C19.2 C23.2 C28.2 C33.2 C34.2 C35.2 C36.2 C43.2 C46.2 C53.2 C54.2 C55.2 C56.2 C58.2 C61.2 C84.2 C86.2 C92.2 C93.2 C95.2 C96.2 C97.2 C98.2 C99.2 C100.2 C101.2 C107.2 C108.2 C110.2 C113.2 C117.2 C118.2 C119.2 C152.2 C159.2 C166.2 C197.2 C207.2 C209.2 C216.2 C217.2 C221.2 C228.2 C230.2 C231.2 C238.2 C248.2 C252.2 C256.2 C258.2 J18.1(CH-GND) J19.1(CH-GND) Q10.4(S1) Q10.7(S2) Q11.4(S1) Q11.7(S2) Q12.4(S1) Q12.7(S2) Q13.4(S1) Q13.7(S2) Q14.4(S1) Q14.7(S2) Q15.4(S1) Q15.7(S2) R22.2 R64.2 R71.2 R72.2 R74.2 R75.2 R76.2 R102.2 R123.2 R132.2 R133.2 R137.2 R138.2 R139.2 R142.2 R145.2 R147.2 R149.2 R151.2 R153.2 R155.2 R157.2 R184.2 R200.2 R221.2 R228.2 R242.2 R250.1 R253.2 R260.2 R267.2 U7.49(GND) U19.49(GND) U34.3(GND) U40.43(GND) U43.3(GND) ; also on sheet 10 11 12 13 14 15 19 20 21 22 23 24 25 26 27 28
VDD_1V1: C17.1 C19.1 C34.1 C55.1 C56.1 C61.1 C95.1 C96.1 C97.1 C98.1 C113.1 C216.1 C217.1 C221.1 C228.1 C256.1 U7.6(VDDA1P1) U7.31(VDD1P1) U7.39(VDD1P1) U19.6(VDDA1P1) U19.31(VDD1P1) U19.39(VDD1P1) ; also on sheet 28
VDD_2V5: C11.1 C23.1 C53.1 C58.1 C92.1 C99.1 C100.1 C107.1 C197.1 C230.1 C231.1 C238.1 U7.3(VDDA2P5) U7.9(VDDA2P5) U19.3(VDDA2P5) U19.9(VDDA2P5) ; also on sheet 28
BP_ADC0_AIN0: R143.1 ; also on sheet 19
BP_ADC0_AIN1: R152.1 ; also on sheet 19
BP_ADC0_AIN2: R144.1 ; also on sheet 19
BP_ADC0_AIN3: R146.1 ; also on sheet 19
BP_ADC0_AIN4: R148.1 ; also on sheet 19
BP_ADC0_AIN5: R150.1 ; also on sheet 19
BP_ADC0_AIN6: R154.1 ; also on sheet 19
BP_ADC0_AIN7: R156.1 ; also on sheet 19
CPSW_RGMII1_RD0: U40.28(C6) ; also on sheet 11
CPSW_RGMII1_RD1: U40.26(C7) ; also on sheet 11
CPSW_RGMII1_RD2: U40.24(C8) ; also on sheet 11
CPSW_RGMII1_RD3: U40.22(C9) ; also on sheet 11
CPSW_RGMII1_RX_CTL: U40.20(C10) ; also on sheet 11
CPSW_RGMII1_RXC: U40.18(C11) ; also on sheet 11
CPSW_RGMII1_TD0: U40.42(C0) ; also on sheet 12
CPSW_RGMII1_TD1: R596.1 R597.1 ; also on sheet 12
CPSW_RGMII1_TD1_MUX: R597.2 U40.40(C1)
CPSW_RGMII1_TD2: U40.37(C2) ; also on sheet 12
CPSW_RGMII1_TD3: U40.35(C3) ; also on sheet 12
CPSW_RGMII1_TX_CTL: R594.1 R595.1 ; also on sheet 12
CPSW_RGMII1_TX_CTL_MUX: R595.2 U40.33(C4)
CPSW_RGMII1_TXC: U40.31(C5) ; also on sheet 12
EPHY1_XI: R13.2 R185.2 U7.20(XI)
ETH1_EARTH: C252.1 J19.15(SH1) J19.16(SH2) R253.1
ETH2_EARTH: C101.1 J18.15(SH1) J18.16(SH2) R200.1
GPIO_RGMII1_PHY_RSTn: R275.1 U43.1(A) ; also on sheet 11
GPIO_RGMII2_PHY_RSTn: R236.1 U34.1(A) ; also on sheet 12
OBSCLK0: R185.1 ; also on sheet 11
PORZ_OUT: U34.2(B) U43.2(B) ; also on sheet 11 12 15 21
PRG1_CPSW_ETH1_CLK_OUT: TP33.1(TP) U19.40(CLK_OUT)
PRG1_CPSW_ETH1_D0M: J19.10(MX0-) U19.2(TD_M_A)
PRG1_CPSW_ETH1_D0P: J19.9(MX0+) U19.1(TD_P_A)
PRG1_CPSW_ETH1_D1M: J19.8(MX1-) U19.5(TD_M_B)
PRG1_CPSW_ETH1_D1P: J19.7(MX1+) U19.4(TD_P_B)
PRG1_CPSW_ETH1_D2M: J19.6(MX2-) U19.8(TD_M_C)
PRG1_CPSW_ETH1_D2P: J19.5(MX2+) U19.7(TD_P_C)
PRG1_CPSW_ETH1_D3M: J19.4(MX3-) U19.11(TD_M_D)
PRG1_CPSW_ETH1_D3P: J19.3(MX3+) U19.10(TD_P_D)
PRG1_CPSW_ETH1_LED1: J19.12 Q13.1(D1) Q13.2(D2) Q13.5(D3) Q13.6(D4) Q13.8(D5)
PRG1_CPSW_ETH1_LED2: J19.13 Q14.1(D1) Q14.2(D2) Q14.5(D3) Q14.6(D4) Q14.8(D5) R252.1
PRG1_CPSW_ETH1_LED3: J19.14 Q15.1(D1) Q15.2(D2) Q15.5(D3) Q15.6(D4) Q15.8(D5) R257.1
PRG1_CPSW_ETH1_LED_1000/RX_ER: Q14.3(G) R138.1 R265.2 U19.46(LED_1/RX_ER) ; also on sheet 12
PRG1_CPSW_ETH1_LED_ACT: Q13.3(G) R137.1 R266.2 R594.2 U19.45(LED_2/GPIO_0)
PRG1_CPSW_ETH1_LED_LINK: R139.1 R264.2 U19.47(LED_0) ; also on sheet 12
PRG1_CPSW_ETH1_RBIAS: R102.1 U19.12(RBIAS)
PRG1_CPSW_ETH2_CLK_OUT: TP11.1(TP) U7.40(CLK_OUT)
PRG1_CPSW_ETH2_D0M: J18.10(MX0-) U7.2(TD_M_A)
PRG1_CPSW_ETH2_D0P: J18.9(MX0+) U7.1(TD_P_A)
PRG1_CPSW_ETH2_D1M: J18.8(MX1-) U7.5(TD_M_B)
PRG1_CPSW_ETH2_D1P: J18.7(MX1+) U7.4(TD_P_B)
PRG1_CPSW_ETH2_D2M: J18.6(MX2-) U7.8(TD_M_C)
PRG1_CPSW_ETH2_D2P: J18.5(MX2+) U7.7(TD_P_C)
PRG1_CPSW_ETH2_D3M: J18.4(MX3-) U7.11(TD_M_D)
PRG1_CPSW_ETH2_D3P: J18.3(MX3+) U7.10(TD_P_D)
PRG1_CPSW_ETH2_LED1: J18.12 Q10.1(D1) Q10.2(D2) Q10.5(D3) Q10.6(D4) Q10.8(D5)
PRG1_CPSW_ETH2_LED2: J18.13 Q11.1(D1) Q11.2(D2) Q11.5(D3) Q11.6(D4) Q11.8(D5) R220.1
PRG1_CPSW_ETH2_LED3: J18.14 Q12.1(D1) Q12.2(D2) Q12.5(D3) Q12.6(D4) Q12.8(D5) R223.1
PRG1_CPSW_ETH2_LED_1000/RX_ER: Q11.3(G) R75.1 R226.2 U7.46(LED_1/RX_ER) ; also on sheet 12
PRG1_CPSW_ETH2_LED_ACT: Q10.3(G) R74.1 R227.2 R596.2 U7.45(LED_2/GPIO_0)
PRG1_CPSW_ETH2_LED_LINK: R76.1 R225.2 U7.47(LED_0) ; also on sheet 12
PRG1_CPSW_ETH2_RBIAS: R22.1 U7.12(RBIAS)
PRG1_CPSW_RGMII1_CLK: U19.20(XI) ; also on sheet 14
PRG1_CPSW_RGMII1_GPIO_1: Q15.3(G) R95.2 R242.1 U19.22(JTAG_TDO/GPIO_1)
PRG1_CPSW_RGMII1_RD0: R123.1 R254.2 U19.33(RX_D0) U40.11(A6)
PRG1_CPSW_RGMII1_RD1: R129.2 R260.1 U19.34(RX_D1) U40.12(A7)
PRG1_CPSW_RGMII1_RD2: R132.1 R269.2 U19.35(RX_D2) U40.13(A8)
PRG1_CPSW_RGMII1_RD3: R133.1 R268.2 U19.36(RX_D3) U40.14(A9)
PRG1_CPSW_RGMII1_RSTn: U19.43(RESET_N) U43.4(Y)
PRG1_CPSW_RGMII1_RX_CTL: R134.2 R267.1 U19.38(RX_CTRL/RX_DV) U40.15(A10)
PRG1_CPSW_RGMII1_RXC: R115.1 U40.16(A11)
PRG1_CPSW_RGMII1_RXC_R: R115.2 U19.32(RX_CLK)
PRG1_CPSW_RGMII1_TD0: U19.28(TX_D0) U40.2(A0)
PRG1_CPSW_RGMII1_TD1: U19.27(TX_D1) U40.3(A1)
PRG1_CPSW_RGMII1_TD2: U19.26(TX_D2) U40.4(A2)
PRG1_CPSW_RGMII1_TD3: U19.25(TX_D3) U40.5(A3)
PRG1_CPSW_RGMII1_TX_CTL: U19.37(TX_CTRL/TX_EN) U40.6(A4)
PRG1_CPSW_RGMII1_TXC: U19.29(GTX_CLK/TX_CLK) U40.7(A5)
PRG1_CPSW_RGMII2_CLK: R13.1 ; also on sheet 14
PRG1_CPSW_RGMII2_GPIO_1: Q12.3(G) R12.2 R184.1 U7.22(JTAG_TDO/GPIO_1)
PRG1_CPSW_RGMII2_RD0: R64.1 R218.2 U7.33(RX_D0) ; also on sheet 12
PRG1_CPSW_RGMII2_RD1: R68.2 R221.1 U7.34(RX_D1) ; also on sheet 12
PRG1_CPSW_RGMII2_RD2: R71.1 R230.2 U7.35(RX_D2) ; also on sheet 12
PRG1_CPSW_RGMII2_RD3: R72.1 R229.2 U7.36(RX_D3) ; also on sheet 12
PRG1_CPSW_RGMII2_RSTn: U7.43(RESET_N) U34.4(Y)
PRG1_CPSW_RGMII2_RX_CTL: R73.2 R228.1 U7.38(RX_CTRL/RX_DV) ; also on sheet 12
PRG1_CPSW_RGMII2_RXC: R51.1 ; also on sheet 12
PRG1_CPSW_RGMII2_RXC_R: R51.2 U7.32(RX_CLK)
PRG1_CPSW_RGMII2_TD0: U7.28(TX_D0) ; also on sheet 12
PRG1_CPSW_RGMII2_TD1: U7.27(TX_D1) ; also on sheet 12
PRG1_CPSW_RGMII2_TD2: U7.26(TX_D2) ; also on sheet 12
PRG1_CPSW_RGMII2_TD3: U7.25(TX_D3) ; also on sheet 12
PRG1_CPSW_RGMII2_TX_CTL: U7.37(TX_CTRL/TX_EN) ; also on sheet 12
PRG1_CPSW_RGMII2_TXC: R23.1 ; also on sheet 12
PRG1_CPSW_RGMII2_TXC_R: R23.2 U7.29(GTX_CLK/TX_CLK)
PRG1_CPSW_RGMII_INTn: R136.2 U7.44(INT_N/PWDN_N) U19.44(INT_N/PWDN_N) ; also on sheet 12
PRG1_MDIO0_MDC: U7.42(MDC) U19.42(MDC) ; also on sheet 12
PRG1_MDIO0_MDIO: R135.2 U7.41(MDIO) U19.41(MDIO) ; also on sheet 12
PRG1_RGMII1_RD0: U40.29(B6) ; also on sheet 12
PRG1_RGMII1_RD1: U40.27(B7) ; also on sheet 12
PRG1_RGMII1_RD2: U40.25(B8) ; also on sheet 12
PRG1_RGMII1_RD3: U40.23(B9) ; also on sheet 12
PRG1_RGMII1_RX_CTL: U40.21(B10) ; also on sheet 12
PRG1_RGMII1_RXC: U40.19(B11) ; also on sheet 12
PRG1_RGMII1_TD0: U40.41(B0) ; also on sheet 12
PRG1_RGMII1_TD1: U40.39(B1) ; also on sheet 12
PRG1_RGMII1_TD2: U40.38(B2) ; also on sheet 12
PRG1_RGMII1_TD3: U40.36(B3) ; also on sheet 12
PRG1_RGMII1_TX_CTL: U40.34(B4) ; also on sheet 12
PRG1_RGMII1_TXC: U40.32(B5) ; also on sheet 12
PRG_CPSW_RGMII1_MUX_SEL: R250.2 U40.9(SEL1) U40.10(SEL2) ; also on sheet 11
SOC_ADC0_AIN0: C28.1 R142.1 R143.2 U18.H21(ADC0_AIN0)
SOC_ADC0_AIN1: C118.1 R152.2 R153.1 U18.F19(ADC0_AIN1)
SOC_ADC0_AIN2: C110.1 R144.2 R145.1 U18.F21(ADC0_AIN2)
SOC_ADC0_AIN3: C108.1 R146.2 R147.1 U18.F20(ADC0_AIN3)
SOC_ADC0_AIN4: C33.1 R148.2 R149.1 U18.H20(ADC0_AIN4)
SOC_ADC0_AIN5: C117.1 R150.2 R151.1 U18.E21(ADC0_AIN5)
SOC_ADC0_AIN6: C35.1 R154.2 R155.1 U18.G20(ADC0_AIN6)
SOC_ADC0_AIN7: C36.1 R156.2 R157.1 U18.E20(ADC0_AIN7)
VSYS_3V3: C6.1 C7.1 C14.1 C43.1 C46.1 C54.1 C84.1 C86.1 C93.1 C119.1 C152.1 C159.1 C166.1 C207.1 C209.1 C248.1 C258.1 R12.1 R68.1 R73.1 R95.1 R129.1 R134.1 R135.1 R136.1 R210.1 R218.1 R220.2 R223.2 R225.1 R226.1 R227.1 R229.1 R230.1 R236.2 R252.2 R254.1 R257.2 R258.1 R264.1 R265.1 R266.1 R268.1 R269.1 R275.2 U7.18(VDDIO) U7.30(VDDIO) U19.18(VDDIO) U19.30(VDDIO) U34.5(VCC) U40.1(VCC) U40.8(EN) U40.17(VCC) U40.30(VCC) U43.5(VCC) ; also on sheet 10 11 12 13 14 15 19 20 21 22 23 24 25 27 28
N30360253: TP25.1(TP) U19.13(VDDA1P8_1) U19.48(VDDA1P8_2)
N30371240: J19.11 R258.2
N30391563: J18.11 R210.2
N30391831: TP4.1(TP) U7.13(VDDA1P8_1) U7.48(VDDA1P8_2)

Not connected (* = marked no-connect by the designer): J18 2(VCC)*; J19 2(VCC)*; U7 14(SON)* 15(SOP)* 16(SIP)* 17(SIN)* 19(XO)* 21(JTAG_CLK/TX_ER)* 23(JTAG_TMS)* 24(JTAG_TDI/SD)*; U19 14(SON)* 15(SOP)* 16(SIP)* 17(SIN)* 19(XO)* 21(JTAG_CLK/TX_ER)* 23(JTAG_TMS)* 24(JTAG_TDI/SD)*

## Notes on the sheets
sheet 16
- CPSW or PRG RGMII1 Ethernet Data MUX
- From SoC
- To Ethernet PHY
- This pin is pulled-down via resistor on BOOTMODE12 Pin
- Interface
- Mount
- DNI
- (From SoC GPIO)
- CPSW_RGMII1_TX_CTL &
  CPSW_RGMII1_TD1
     (Default)
- R595, R597
- R594, R596
- SEL1 & SEL2
- Path
- Interface
- Low (0)
- B0 to B11 --> A0 to A 11
- PRG1_RGMII1 (Default)
- PRG1_CPSW_ETH1_LED_ACT &
  PRG1_CPSW_ETH2_LED_ACT
- R594, R596
- R595, R597
- High (1)
- C0 to C11 --> A0 to A 11
- CPSW_RGMII1
- ADC Inputs
sheet 17
- PRG / CPSW RGMII1 Ethernet PHY
- RJ45 Connector with Integrated Magnetics
- RGMII1 PHY Strapping Resistors
- RGMII1 PHY Speed & Activity LED Drivers
- PHY ADDRESS = 00011
- Auto-negotiation, 10/100/1000 advertised, Auto-MDI-X
- RGMII to Copper (1000BaseT/100Base-TX/10Base-Te)
- RGMII1 PHY Reset
- (From SoC GPIO)
sheet 18
- RJ45 Connector with Integrated Magnetics
- PRG / CPSW RGMII2 Ethernet PHY
- OBSCLK is used to source the RGMII2 Ethernet PHY
- Mount R240 & R185 and DNI R244 & R13 to source the RGMII2
  Ethernet PHY from OBSCLK
- RGMII2 PHY Strapping Resistors
- RGMII2 PHY Speed & Activity LED Drivers
- PHY ADDRESS = 01111
- Auto-negotiation, 10/100/1000 advertised, Auto-MDI-X
- RGMII to Copper (1000BaseT/100Base-TX/10Base-Te)
- RGMII2 PHY Reset
- (From SoC GPIO)
